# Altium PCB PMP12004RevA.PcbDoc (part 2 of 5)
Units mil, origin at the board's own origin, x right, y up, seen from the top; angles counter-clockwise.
Board outline 5500 x 4500 mil, 6 copper layers (Top Layer, GND, Signal Layer 1, Signal Layer 2, PWR Split, Bottom Layer), stack 0 mil thick; 355 components, 130 nets, 833 pads, 904 vias.
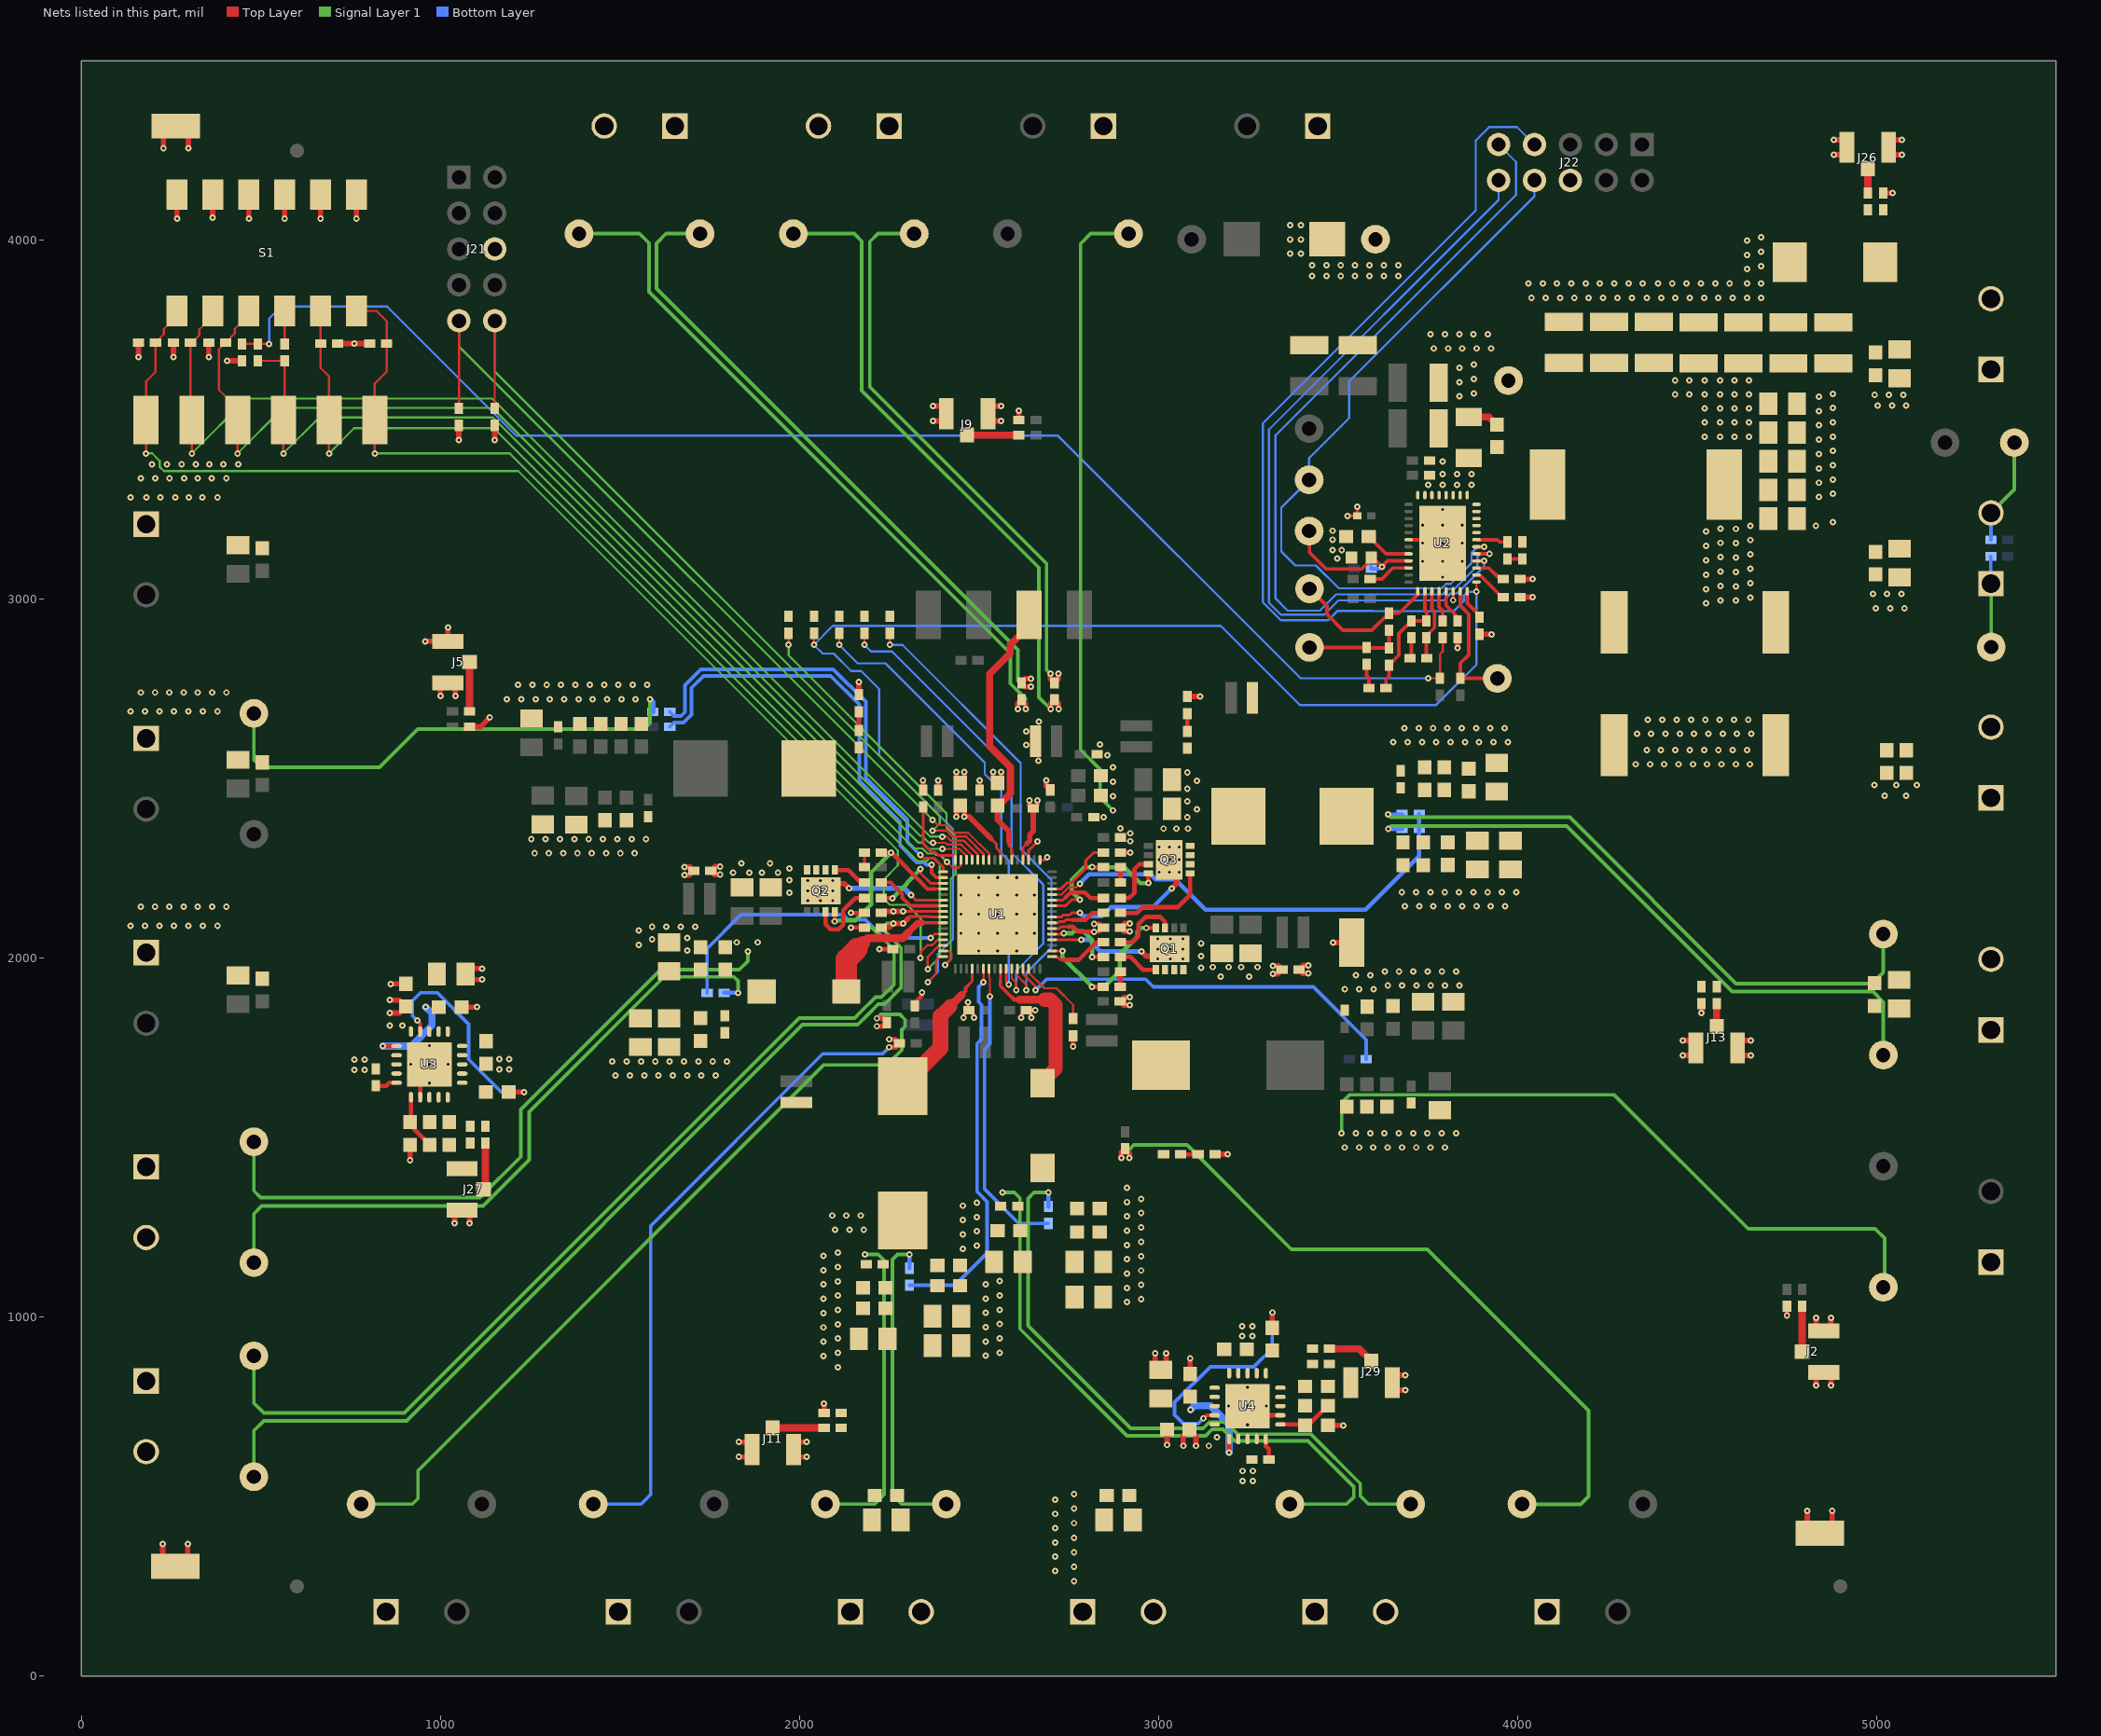
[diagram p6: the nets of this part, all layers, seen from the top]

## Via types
v1: diameter 18, hole 8, Top Layer to Bottom Layer, tented both sides, 835 vias
v2: diameter 19.68, hole 8.01, Top Layer to Bottom Layer, tented bottom, 42 vias
v3: diameter 18, hole 8.01, Top Layer to Bottom Layer, tented bottom, 27 vias

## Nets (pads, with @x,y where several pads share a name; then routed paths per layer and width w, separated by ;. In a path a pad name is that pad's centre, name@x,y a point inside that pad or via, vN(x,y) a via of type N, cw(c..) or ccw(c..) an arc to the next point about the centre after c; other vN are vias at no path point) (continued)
BUCK3_OUT: C132.1 C133.1 C134.1 C135.1 C136.1 C137.1 C138.1 C139.1 C140.1 C141.1 L6.2 R80.2 TP49.1 U3.5 U3.6 U3.7 U3.8 U3.11 | length 2170.3
  Top Layer w12: v1(839.77,1755.42) U3.11@877.43,1755.42
  Signal Layer 1 w10: TP49.1@480,1152.02 480,1287.83 501.93,1309.76 983.98,1309.76 1118.23,1309.76 1246.79,1438.31 1246.79,1572.56 1622.57,1948.34 1817.82,1948.34 1828.64,1937.52 v1(1828.64,1903.59)
  Bottom Layer w12: R80.2@1789.84,1903.59 v1(1828.64,1903.59)
  Bottom Layer w20: v1(839.77,1755.42) 918.91,1755.42 976.29,1812.79 976.29,1846.56 v1(958.82,1864.03)
BUCK4_OUT: C146.1 C148.1 C149.1 C150.1 C151.1 C152.1 C153.1 C154.1 C155.1 C156.1 L7.2 R85.2 TP51.1 U4.5 U4.6 U4.7 U4.8 U4.11 | length 2011.8
  Top Layer w12: v1(3196.98,622.99) U4.11@3196.98,660.65
  Signal Layer 1 w10: v1(2693.42,1347.02) 2653.19,1347.02 2637.07,1330.9 2637.07,975.98 2922.58,690.47 3124.72,690.47 3142.02,707.77 3187.41,707.77 3221.42,673.76 3425.05,673.76 3562.54,536.28 3562.54,501.81 3585.35,479 TP51.1@3702.83,479
  Bottom Layer w12: R85.2@2693.42,1308.22 v1(2693.42,1347.02)
  Bottom Layer w20: v1(3089.59,741.7) 3100.73,752.84 3144.8,752.84 3196.98,700.66 v1(3196.98,622.99)
BUCK5_OUT: C53.1 C54.1 C56.1 C57.1 C58.1 C59.1 C60.1 C61.1 C62.1 C63.1 C64.1 C65.1 C66.1 J8.2 J12.2 L3.2 R1.1 R3.1 R38.1 R39.2 TP21.1 | length 908.6
  Signal Layer 1 w10: v1(2306.42,1175.02) 2273.72,1175.02 2258.86,1160.16 2258.86,505.25 2285.11,479 TP21.1@2409.13,479
  Bottom Layer w12: R39.2@2306.42,1136.22 v1(2306.42,1175.02)
  other v1: 2099.57,1243.77 2139.54,1243.77 2179.12,1243.77 2091.03,1283.14 2130.87,1283.14 2170.71,1283.14 2665.65,2550.44 2631.96,2594.59 2631.96,2632.59 2666.49,2659
BUCK6_OUT: C74.1 C75.1 C76.1 C77.1 C78.1 C79.1 C80.1 C81.1 C82.1 C83.1 C84.1 C85.1 C86.1 J14.2 L4.2 R7.1 R45.1 R47.2 TP25.1 | length 1732.3
  Signal Layer 1 w10: v1(3639.99,2400.59) 3647.93,2392.66 4146.27,2392.66 4609.18,1929.75 4988.09,1929.75 5019.33,1961 TP25.1@5019.33,2067.19
  Bottom Layer w12: v1(3639.99,2400.59) R47.2@3678.8,2400.59
CLK: J22.9 U2.5 | length 2289.6
  Top Layer w10: U2.5@3885.96,3126.85 v1(3922.24,3126.85)
  Bottom Layer w6: v1(3922.24,3126.85) 3896.96,3126.85 3888.15,3118.04 3888.15,3092.59 3824.81,3029.26 3806.9,3029.26 3791.75,3014.1 3495.14,3014.1 3449.6,2968.56 3360.11,2968.56 3326.39,3002.28 3326.39,3457.42 3996.31,4127.35 3996.31,4218.77 J22.9@3947.51,4267.57
CTL1: R10.1 S1.1 TP6.1 U1.13 | length 3474.8
  Top Layer w6: v1(179.93,3406.75) TP6.1@179.93,3499.79 179.93,3607.58 205.93,3633.58 R10.1@205.93,3715.79 229.44,3739.3 229.44,3753.87 265.93,3790.36 S1.1@265.93,3803.79 ; v1(2337.29,2000.73) 2337.29,2017.77 2356.21,2036.69 2370.43,2036.69 2385.34,2051.6 U1.13@2400.42,2051.6
  Signal Layer 1 w6: v1(179.93,3406.75) 196.86,3406.75 217.37,3386.23 217.37,3369.65 229.4,3357.61 1216.38,3357.61 2274.07,2299.92 2274.07,2258.53 2235.34,2219.79 2235.34,2165.55 2252.14,2148.75 2300.16,2148.75 2337.29,2111.62 v1(2337.29,2000.73)
CTL2: R16.1 S1.2 TP12.1 U1.60 | length 3220.6
  Top Layer w6: v1(307.33,3406.75) TP12.1@307.33,3499.79 303.55,3503.57 R16.1@303.55,3715.79 307.43,3715.79 327.93,3736.29 327.93,3752.66 365.93,3790.66 S1.2@365.93,3803.79 ; v1(2397.73,2338.94) 2410.33,2338.94 2421.45,2327.81 2458.09,2327.81 2496.87,2289.03 U1.60@2496.87,2274.04
  Signal Layer 1 w6: v1(307.33,3406.75) 459.89,3559.31 1143.67,3559.31 2364.04,2338.94 v1(2397.73,2338.94)
CTL3/SLPENB1: R14.1 S1.3 TP9.1 U1.61 | length 3080.5
  Top Layer w6: v1(434.73,3406.75) TP9.1@434.73,3499.79 434.73,3531.98 382.97,3583.74 382.97,3697.21 R14.1@401.55,3715.79 401.91,3715.79 427.12,3741.01 427.12,3753.43 465.93,3792.23 S1.3@465.93,3803.79 ; v1(2371.96,2321.78) 2406.67,2321.78 2411.64,2316.81 2450.23,2316.81 2481.13,2285.91 U1.61@2481.13,2274.04
  Signal Layer 1 w6: v1(434.73,3406.75) 561.41,3533.43 1144.26,3533.43 2336.55,2341.14 2341.54,2341.14 2360.9,2321.78 v1(2371.96,2321.78)
CTL4: R12.2 R19.1 TP7.1 U1.62 | length 2802.4
  Top Layer w6: R12.2@490.86,3664.63 R19.1@565.93,3664.63 565.93,3497.73 TP7.1@562.13,3493.93 ; v1(562.13,3406.75) TP7.1@562.13,3493.93 ; TP7.1@562.13,3499.79 TP7.1@562.13,3493.93 ; v1(2397.73,2304.78) 2445.62,2304.78 2465.38,2285.02 U1.62@2465.38,2274.04
  Signal Layer 1 w6: v1(562.13,3406.75) 662.53,3507.15 1145.89,3507.15 2330.36,2322.67 2342.21,2322.67 2360.1,2304.78 v1(2397.73,2304.78)
CTL4_2: R11.1 R12.1 R58.2 R60.1 | length 3966.9
  Top Layer w6: R11.1@446.92,3711.79 R12.1@490.86,3711.79 ; R12.1@490.86,3711.87 v1(522.87,3711.87) ; v1(3751.7,2780) R58.2@3784.23,2780 3784.23,2847.22 3792,2854.99 R60.1@3792,2892.76
  Bottom Layer w6: v1(522.87,3711.87) 522.87,3782.99 555.57,3815.69 851.46,3815.69 1211.18,3455.96 2720.18,3455.96 3396.14,2780 v1(3751.7,2780)
CTL5: R13.1 S1.5 TP8.1 U1.63 | length 2720.9
  Top Layer w6: S1.5@665.93,3803.79 665.93,3644.8 689.53,3621.19 TP8.1@689.53,3499.79 v1(689.53,3406.75) ; v1(2410.91,2268.56) 2427.2,2252.26 2442.65,2252.26 2449.63,2259.25 U1.63@2449.63,2274.04
  Signal Layer 1 w6: v1(689.53,3406.75) 759.64,3476.86 1148.62,3476.86 2319.43,2306.05 2342.34,2306.05 2356.79,2291.6 2377.36,2291.6 2381.19,2287.78 2391.68,2287.78 v1(2410.91,2268.56)
CTL6/SLPENB2: R17.1 S1.6 TP14.1 U1.14 | length 2878.3
  Top Layer w6: S1.6@765.93,3803.79 821.59,3803.79 850.05,3775.33 R17.1@850.05,3712.79 850.05,3634.75 816.93,3601.62 TP14.1@816.93,3549.79 ; v1(816.93,3406.75) TP14.1@816.93,3499.79 ; v1(2357.37,1970.01) 2357.42,2004.09 2389.19,2035.85 U1.14@2400.42,2035.85
  Signal Layer 1 w6: v1(816.93,3406.75) 1192.9,3406.75 2329.29,2270.36 2353.85,2270.36 2360.95,2277.47 2375.03,2277.47 2391.09,2261.41 2391.09,2003.74 v1(2357.37,1970.01)
DATA: J22.10 U2.4 | length 2147.3
  Top Layer w10: U2.4@3885.96,3107.17 v1(3907.28,3107.17)
  Bottom Layer w6: v1(3907.28,3107.17) 3907.28,3091.72 3832.07,3016.5 3814.12,3016.5 3794.74,2997.12 3501.56,2997.12 3461.99,2957.56 3341.02,2957.56 3307.88,2990.7 3307.88,3473.02 3947.51,4112.65 J22.10@3947.51,4167.57
DRV5V_1_6: C3.1 R8.2 U1.38 | length 247.2
  Top Layer w8: U1.38@2703.57,2083.1 2724.26,2083.1 2728.87,2087.71 2750.64,2087.71
  Top Layer w12: 2750.64,2087.71 2762.82,2087.71 2776.54,2073.99 v1(2820.79,2073.99) 2835.19,2073.99 C3.1@2846.8,2085.59 2836.28,2096.11 v1(2820.79,2096.11)
  Top Layer w15: v1(3318.41,1956.99) 3332.82,1956.99 R8.2@3344.42,1968.59 3333.91,1979.11 v1(3318.41,1979.11)
DRV5V_2_A1: C2.1 R9.2 U1.8 | length 235.1
  Top Layer w8: v1(2288.87,2130.34) U1.8@2400.42,2130.34
  Top Layer w15: v1(1779.05,2233.08) 1763.55,2233.08 R9.2@1753.04,2243.59 1764.64,2255.2 v1(1779.05,2255.2) ; C2.1@2228.04,2126.59 2231.79,2130.34 v1(2261.42,2130.34) v1(2288.87,2130.34)
DRVH1: R22.1 U1.33 | length 167.3
  Top Layer w8: U1.33@2703.57,2004.36 2717.94,2004.36 2726.84,1995.46 2736.26,1995.46 2736.45,1995.65
  Top Layer w12: 2736.45,1995.65 2777.8,1995.65 2826.74,2044.59 R22.1@2846.8,2044.59
DRVH2: R30.1 U1.3 | length 230.6
  Top Layer w8: v1(2336.99,2248.47) 2336.99,2237.4 2365.31,2209.08 U1.3@2400.42,2209.08
  Top Layer w12: R30.1@2228.04,2167.59 v1(2259.42,2167.59)
  Signal Layer 1 w12: v1(2259.42,2167.59) 2299.54,2207.72 2299.54,2211.02 v1(2336.99,2248.47)
DRVH6: R43.1 U1.43 | length 158.7
  Top Layer w8: U1.43@2703.57,2161.84 2733.77,2161.84 2741.13,2169.2
  Top Layer w12: 2741.13,2169.2 2742.01,2170.08 2742.2,2170.08 2755.51,2183.4 2795.26,2183.4 2811.06,2167.59 R43.1@2846.8,2167.59
DRVL1: R23.1 U1.37 | length 203.9
  Top Layer w8: U1.37@2703.57,2067.35 2733.96,2067.35 v1(2736.32,2069.71)
  Top Layer w12: v1(2815.5,2003.59) R23.1@2846.8,2003.59
  Signal Layer 1 w12: v1(2736.32,2069.71) 2759.42,2069.71 2765.36,2075.65 2790.27,2075.65 2815.5,2050.42 v1(2815.5,2003.59)
DRVL2: R31.1 U1.7 | length 205.3
  Top Layer w8: 2385.05,2146.09 U1.7@2400.42,2146.09
  Top Layer w10: R31.1@2228.04,2211.59 2253.42,2211.59 2286.51,2178.5 2286.51,2168.67 2309.09,2146.09 2385.05,2146.09
DRVL6: R44.1 U1.39 | length 154.7
  Top Layer w8: U1.39@2703.57,2098.85 2721.62,2098.85 2724.37,2101.59 2736.78,2101.59 2742.17,2106.99 2760.78,2106.99
  Top Layer w12: 2760.78,2106.99 2796.64,2106.99 2816.24,2126.59 R44.1@2846.8,2126.59
FB3: R80.1 U1.12 | length 851.7
  Top Layer w6: v1(2365.23,2056.92) 2375.66,2067.35 U1.12@2400.42,2067.35
  Bottom Layer w10: R80.1@1742.6,1903.59 1742.6,2027.16 1837.17,2121.74 2121.4,2121.74 2135.55,2107.59 2183.9,2107.59 2234.58,2056.92 v1(2365.23,2056.92)
FB4: R85.1 U1.23 | length 838.4
  Top Layer w6: U1.23@2528.37,1970.89 2528.37,1946.43 2530.24,1944.57 v1(2530.24,1893.65)
  Bottom Layer w10: v1(2530.24,1893.65) 2530.24,1761.33 2515.74,1746.83 2515.74,1356.46 2611.22,1260.97 R85.1@2693.42,1260.97
FB5: R39.1 U1.22 | length 1071.8
  Top Layer w6: v1(2512.62,1933.41) U1.22@2512.62,1970.89
  Bottom Layer w10: R39.1@2306.42,1088.97 2432.91,1088.97 2523.51,1179.57 2522.7,1180.38 2522.7,1321.59 2494.63,1349.66 2494.63,1762.28 2506.86,1774.51 2506.86,1870.34 2499.14,1878.06 2499.14,1919.93 v1(2512.62,1933.41)
FBGND2: R35.1 U1.1 | length 1266.7
  Top Layer w8: v1(2336.99,2287.36) 2345.6,2278.75 2375.26,2278.75 2400.42,2253.59 U1.1@2400.42,2240.58
  Bottom Layer w10: R35.1@1638.66,2686.22 1649.53,2675.35 1669.92,2675.35 1680.68,2686.11 1680.68,2761.01 1724.91,2805.24 2094.47,2805.24 2184.73,2714.98 2184.73,2501.8 2300.43,2386.11 2300.43,2323.92 v1(2336.99,2287.36)
FBVOUT1: R26.1 U1.29 | length 1131.2
  Top Layer w6: U1.29@2622.86,1970.89 2622.86,1956.88 2658.06,1921.68 v1@2658.06,1912.29
  Bottom Layer w10: v1(2658.06,1911.13) 2688.79,1941.87 2963.86,1941.87 2985.83,1919.9 3432.06,1919.9 3579.04,1772.91 R26.1@3579.04,1718.59
FBVOUT2: R34.1 U1.2 | length 1275
  Top Layer w8: U1.2@2390.82,2225.18 2391.17,2224.83 U1.2@2400.42,2224.83
  Top Layer w10: v1(2367.99,2260.47) 2367.99,2237.72 2380.88,2224.83 U1.2@2391.17,2224.83
  Bottom Layer w10: R34.1@1638.66,2645.22 1650.51,2657.07 1677.5,2657.07 1698.97,2678.54 1698.97,2753.44 1732.48,2786.96 2086.9,2786.96 2166.45,2707.4 2166.45,2494.23 2280.37,2380.31 2280.37,2313.46 2326.36,2267.47 2346.14,2267.47 2353.14,2260.47 v1(2367.99,2260.47)
FBVOUT6: R47.1 R48.2 U1.44 | length 1266.4
  Top Layer w6: U1.44@2703.57,2177.59 2729.71,2177.59 2736.21,2184.08 2736.4,2184.08 2749.71,2197.4 2770.63,2197.4 v1(2780.69,2207.45)
  Bottom Layer w12: v1(2780.69,2207.45) 2806.82,2233.59 2977.71,2233.59 2991.93,2219.38 3046.42,2219.38 3130.81,2134.99 3577.26,2134.99 3726.4,2284.13 R48.2@3726.4,2360.47 R47.1@3726.4,2401.91
GND: C1.2 C2.2 C3.2 C4.2 C5.2 C6.2 C7.2 C8.2 C9.2 C10.2 C11.2 C12.2 C13.2 C14.2 C15.2 C16.2 C17.2 C19.2 C20.2 C21.2 C22.2 C23.2 C24.2 C25.2 C26.2 C27.2 C28.2 C29.2 C30.2 C32.2 C33.2 C34.2 C35.2 C36.2 C37.2 C38.2 C39.2 C40.2 C41.2 C42.2 C43.2 C44.2 C45.2 C46.2 C47.2 C48.2 C49.2 C50.2 C51.2 C52.2 C53.2 C54.2 C55.2 C56.2 C57.2 C58.2 C59.2 C60.2 C61.2 C62.2 C63.2 C64.2 C65.2 C66.2 C67.2 C68.2 C69.2 C70.2 C72.2 C73.2 C74.2 C75.2 C76.2 C77.2 C78.2 C79.2 C80.2 C81.2 C82.2 C83.2 C84.2 C85.2 C86.2 C87.2 C88.2 C89.2 C90.2 C91.2 C92.2 C93.2 C97.2 C98.2 C99.2 C101.2 C102.2 C103.2 C104.2 C105.2 C106.2 C107.2 C108.2 C111.2 C112.2 C113.2 C114.2 C115.2 C116.2 C117.2 C118.2 C119.2 C120.2 C121.2 C122.2 C123.2 C124.2 C125.2 C126.2 C127.2 C128.2 C129.2 C130.2 C131.2 C132.2 C133.2 C134.2 C135.2 C136.2 C137.2 C138.2 C139.2 C140.2 C141.2 C142.2 C143.2 C144.2 C145.2 C146.2 C147.2 C148.2 C149.2 C150.2 C151.2 C152.2 C153.2 C154.2 C155.2 C156.2 C157.2 C158.2 J1.1 J2.2 J2.3 J3.1 J4.1 J5.2 J5.3 J6.1 J7.1 J8.1 J9.2 J9.3 J10.1 J11.2 J11.3 J12.1 J13.2 J13.3 J14.1 J15.1 J16.1 J17.1 J18.1 J19.1 J20.1 J21.6 J22.6 J23.1 J24.1 J25.1 J26.2 J26.3 J27.2 J27.3 J28.1 J29.2 J29.3 J30.1 Q1.9 Q2.9 Q3.9 R27.2 R35.2 R36.2 R48.1 R49.2 R62.2 R65.2 R67.2 R69.2 R73.2 R75.1 R79.1 R84.1 S1.7 S1.8 S1.9 S1.10 S1.11 S1.12 TP2.1 TP3.1 TP4.1 TP5.1 TP18.1 TP20.1 TP22.1 TP24.1 TP26.1 TP30.1 TP31.1 TP32.1 TP36.1 TP37.1 TP38.1 TP48.1 TP50.1 TP52.1 U1.6 U1.36 U1.40 U1.52 U1.65 U2.13 U2.14 U2.15 U2.16 U2.17 U2.18 U2.19 U2.20 U2.26 U2.38 U2.41 U3.2 U3.3 U3.4 U3.12 U3.13 U3.14 U3.17 U3.21 U4.2 U4.3 U4.4 U4.12 U4.13 U4.14 U4.17 U4.21 | length 30114.8
  Top Layer w8: v1(2310.49,2175.97) 2324.62,2161.84 U1.6@2400.42,2161.84 ; U1.52@2622.86,2274.04 2622.86,2308.53 2634.37,2320.05 ; U1.36@2703.57,2051.6 v1(2785.08,2051.6) ; U1.40@2703.57,2114.59 2729.05,2114.59 2734.55,2120.09 2752.67,2120.09 2759.92,2127.34 v1(2780.69,2127.34)
  Top Layer w10: v1(2457.01,1834.29) 2457.01,1840.81 C7.2@2471.8,1855.59 ; v1(2469.55,1876.94) 2469.55,1857.84 C7.2@2471.8,1855.59 ; v1(2486.12,1834.29) 2486.12,1841.27 C7.2@2471.8,1855.59 ; v1(2617.25,1834.29) 2617.25,1840.81 C6.2@2632.04,1855.59 ; v1(2646.36,1834.29) 2646.36,1841.27 C6.2@2632.04,1855.59 ; v1(2657.03,1854.88) 2656.32,1855.59 C6.2@2632.04,1855.59 ; v1(3526.68,3232.68) C108.2@3553.59,3232.68 v1(3553.6,3258) ; U2.26@3696.98,3166.22 3781.63,3166.22 v2(3791.47,3156.38) ; v1(3821,2997.73) U2.38@3821,3022.52
  Top Layer w12: U3.17@943.37,1612.7 943.37,1678.65 v2(968.96,1704.24) ; v1(2143.42,2085.59) C88.2@2180.8,2085.59 ; v1(2143.42,2126.59) C2.2@2180.8,2126.59 ; v1(2222.8,2025.59) C5.2@2260.17,2025.59 ; C10.2@2320.92,1867.22 2320.92,1875.28 2341.58,1895.94 v1(2341.58,1904.3) ; R49.2@2894.04,2294.59 v1(2921.09,2294.59) ; v2(3248.17,752.19) 3273.76,726.6 U4.17@3339.7,726.6
  Top Layer w15: v1(226.37,368.2) 226.37,306.07 TP3.1@261.14,306.07 295.91,306.07 v1(295.91,368.2) ; v1(228.16,4256.66) 228.16,4318.79 TP5.1@262.93,4318.79 297.7,4318.79 v1(297.7,4256.66) ; v1(265.93,4060.69) S1.12@265.93,4127.79 ; v1(364.99,4063.15) S1.11@364.99,4130.25 ; v1(465.93,4060.69) S1.10@465.93,4127.79 ; v1(565.93,4060.69) S1.9@565.93,4127.79 ; v1(665.93,4060.69) S1.8@665.93,4127.79 ; v1(765.93,4060.69) S1.7@765.93,4127.79 ; v1(860.92,1928.53) C143.2@903.96,1928.53 ; v1(915.26,1437.3) R79.1@915.26,1480.34 ; v1(957.69,2883.29) 1014.69,2883.29 J5.3@1017.64,2886.24 ; v1(999.8,2730.6) 999.8,2767.15 J5.2@1020.59,2767.15 1041.39,2767.15 v1(1041.39,2730.6) ; J5.3@1020.59,2883.29 v1(1020.59,2921.69) ; v1(1039.17,1261.16) 1039.17,1297.71 J27.2@1059.96,1297.71 1080.76,1297.71 v1(1080.76,1261.16) ; C141.2@1058.46,1864.03 v1(1101.5,1864.03) ; C49.2@1080.63,2645.31 1111.88,2645.31 v1(1137.28,2670.7) ; v1(1115.85,1940.64) 1085.36,1940.64 C140.2@1069.97,1956.03 1085.36,1971.43 v1(1115.85,1971.43) ; v1(1830.95,610.5) 1867.5,610.5 J11.3@1867.5,631.29 1867.5,652.08 v1(1830.95,652.08) ; v1(2020.19,610.5) 1983.64,610.5 J11.2@1983.64,631.29 1983.64,652.08 v1(2020.19,652.08) ; Q2.9@2059.8,2187.59 2080.26,2208.06 2125.37,2208.06 v1(2138.36,2195.07) ; C64.2@2068.6,733.53 v1(2068.6,759.55) ; C50.2@2165.22,2734.37 v1(2165.22,2769.82) ; v1(2215.41,1810.46) 2232.91,1810.46 C91.2@2243.42,1820.97 2231.82,1832.57 v1(2215.41,1832.57) ; v1(2250.17,1752.08) 2267.66,1752.08 C92.2@2278.17,1762.59 2266.57,1774.2 v1(2250.17,1774.2) ; v1(2344.01,2495.96) 2344.42,2495.55 R36.2@2344.42,2468.84 ; v1(2372.5,3496.93) 2409.05,3496.93 J9.2@2409.05,3517.72 2409.05,3538.52 v1(2372.5,3538.52) ; v1(2386.01,2495.96) 2386.42,2495.55 C15.2@2386.42,2468.84 ; v1(2437.38,2518.59) 2437.38,2499.63 C13.2@2448.42,2488.59 2459.49,2499.66 v1(2459.49,2518.59) ; v1(2502.01,2495.96) 2502.42,2495.55 C11.2@2502.42,2468.84 ; v1(2539.77,2519.28) 2539.77,2500.23 C14.2@2551.42,2488.59 2561.89,2499.06 v1(2561.89,2519.28) ; v1(2561.74,3496.93) 2525.19,3496.93 J9.3@2525.19,3517.72 2525.19,3538.52 v1(2561.74,3538.52) ; C55.2@2611.46,3499.8 v1(2611.46,3525.82) ; 2634.37,2320.05 2641.31,2326.99 2641.31,2344.18 2651.42,2354.28 C12.2@2651.42,2417.59 ; v1(2640.34,2440.32) 2640.34,2428.67 C12.2@2651.42,2417.59 ; v1(2644.43,2756.7) 2628.93,2756.7 C89.2@2618.42,2767.22 2630.02,2778.82 v1(2644.43,2778.82) ; v1(2662.46,2440.32) 2662.46,2428.63 C12.2@2651.42,2417.59 ; v1(2687.19,2495.22) 2687.19,2480.82 C8.2@2698.8,2469.22 ; v1(2698.82,2793.22) 2698.82,2778.82 C90.2@2710.42,2767.22 2720.93,2777.73 v1(2720.93,2793.22) ; v1(2762.42,1754.15) R27.2@2762.42,1784.35 ; v1(2896.91,1443.34) 2896.91,1458.84 C93.2@2907.42,1469.35 2919.02,1457.75 v1(2919.02,1443.34) ; v1(2919.67,1869.08) 2904.18,1869.08 C9.2@2893.66,1879.59 2905.27,1891.2 v1(2919.67,1891.2) ; v1(2920.05,2075.08) 2904.55,2075.08 C3.2@2894.04,2085.59 2905.64,2097.2 v1(2920.05,2097.2) ; v1(2952.65,2018.85) 2965.64,2005.86 3010.75,2005.86 Q1.9@3031.21,2026.33 ; v1(2990.97,899.08) 2990.97,868.59 C155.2@3006.37,853.19 3021.76,868.59 v1(3021.76,899.08) ; v1(3023.87,644.15) C157.2@3023.87,687.19 ; Q3.9@3029.65,2273.19 3050.11,2252.73 3050.11,2207.61 v1(3037.13,2194.63) ; C87.2@3080.48,2729.15 v1(3115.94,2729.15) ; C156.2@3088.37,841.69 v1(3088.37,884.73) ; C30.2@3157.66,1453.59 v1(3193.12,1453.59) ; R84.1@3472.06,698.49 v1(3515.1,698.49) ; J29.3@3535.36,796.73 J29.3@3535.36,817.52 J29.3@3535.36,838.32 ; v1(3688.05,796.73) 3651.5,796.73 J29.2@3651.5,817.52 3651.5,838.32 v1(3688.05,838.32) ; v1(3833,2865) R62.2@3833,2892.76 ; R65.2@3894.23,2902.76 v1(3928.3,2902.76) ; R67.2@4007.85,3006.38 v1(4041.92,3006.38) ; R69.2@4007.85,3056.38 v1(4041.92,3056.38) ; v1(4460.63,1729.12) 4497.18,1729.12 J13.3@4497.18,1749.91 4497.18,1770.71 v1(4460.63,1770.71) ; v1(4513.05,1847.8) C86.2@4513.05,1873.82 ; v1(4649.87,1729.12) 4613.32,1729.12 J13.2@4613.32,1749.91 4613.32,1770.71 v1(4649.87,1770.71) ; v1(4751.01,1004.25) C29.2@4751.01,1030.27 ; v1(4807.38,459.9) 4807.38,397.77 TP4.1@4842.15,397.77 4876.92,397.77 v1(4876.92,459.9) ; v1(4832.46,809.27) 4832.46,845.83 J2.3@4853.25,845.83 4874.05,845.83 v1(4874.05,809.27) ; v1(4832.46,998.52) 4832.46,961.97 J2.2@4853.25,961.97 4874.05,961.97 v1(4874.05,998.52) ; v1(4881.51,4239.05) 4918.06,4239.05 J26.2@4918.06,4259.85 4918.06,4280.64 v1(4881.51,4280.64) ; C130.2@5019.68,4132.61 v1(5045.7,4132.61) ; v1(5070.75,4239.05) 5034.2,4239.05 J26.3@5034.2,4259.85 5034.2,4280.64 v1(5070.75,4280.64)
  Signal Layer 1 w10: TP30.1@480,892.02 480,760.58 507.84,732.74 898.65,732.74 1999.22,1833.32 2153.49,1833.32 2169.81,1849.64 2211.78,1891.59 2227.83,1891.59 2263.43,1927.2 2263.43,2023.65 2201.48,2085.59 v1(2143.42,2085.59) ; TP50.1@480,1488.87 480,1352.11 499.39,1332.72 1109.44,1332.72 1223.6,1446.88 1223.6,1578.19 1613.44,1968.02 1832.39,1968.02 1856.53,1992.17 v1(1856.53,2019.01) ; TP20.1@480,2682.57 480,2552.13 499.95,2532.18 830.31,2532.18 936.32,2638.19 1566.12,2638.19 1583.53,2655.6 v1(1583.53,2722.15) ; TP36.1@778.58,479 921.64,479 937.45,494.81 937.45,572.2 2068.14,1702.89 2243.49,1702.89 2284.83,1744.23 2284.83,1800.71 2294.65,1810.53 2294.65,1828.62 2279.97,1843.3 2226.14,1843.3 v1(2215.41,1832.57) ; TP32.1@1722.87,4019 1628.46,4019 1601.89,3992.43 1601.89,3866.2 2608.66,2859.44 2608.66,2773.79 2625.74,2756.7 v1(2644.43,2756.7) ; TP22.1@2072.28,479 2209.56,479 2235.95,505.39 2235.95,1158.55 2219.49,1175.02 v1(2182.26,1175.02) ; TP31.1@2319.72,4019 2218.45,4019 2196.09,3996.63 2196.09,3591.82 2688.46,3099.45 2688.46,2803.58 v1(2698.82,2793.22) ; v1(2565.57,1347.02) 2598.74,1347.02 2614.34,1331.43 2614.34,967.66 2912.44,669.56 3131.65,669.56 3149.3,687.22 3180.08,687.22 3212.01,655.29 3416.08,655.29 3544.49,526.88 3544.49,499.6 3523.89,479 TP52.1@3365.98,479 ; v1(2873.26,2411.86) 2837.86,2447.26 2837.86,2525.9 2782.96,2580.8 2782.96,3990.53 2811.44,4019 TP24.1@2916.57,4019 ; v1(2919.02,1443.34) 2919.02,1467.23 2931.36,1479.57 3079.87,1479.57 3370.39,1189.05 3748.44,1189.05 4198.06,739.43 4198.06,500.18 4176.09,478.21 4013.61,478.21 TP38.1@4012.83,479 ; v1(3510.39,1512.21) 3510.39,1597.77 3532,1619.38 4269.89,1619.38 4643.12,1246.14 4996.54,1246.14 5022.86,1219.82 5022.86,1087.02 TP18.1@5019.33,1083.49 ; v1(3640.36,2360.47) 3648.38,2368.5 4137.01,2368.5 4598.48,1907.03 4990.21,1907.03 5019.33,1877.91 TP26.1@5019.33,1730.34 ; J24.1@5319.33,3044.04 5320.09,3043.29 TP48.1@5320.09,2867.18
  Bottom Layer w10: TP37.1@1425.43,479 1558.54,479 1585.34,505.8 1585.34,1254.34 2064.79,1733.78 2231.87,1733.78 v1(2250.17,1752.08) v1@2250.17,1750.99 ; v1@2215.41,1809.37 v1(2215.41,1810.46) ; R73.2@5318.8,3119.79 5318.8,3044.58 J24.1@5319.33,3044.04
  Bottom Layer w12: v1(2780.69,2127.34) 2790.81,2117.21 2841.92,2117.21 2867.12,2142.42 2984.92,2142.42 v1(3037.13,2194.63) ; v1(2785.08,2051.6) 2806.55,2051.6 2839.3,2018.85 v1(2952.65,2018.85) ; v1(3640.36,2360.47) R48.1@3679.16,2360.47
  Bottom Layer w15: v1(1583.53,2722.15) 1591.42,2714.26 R35.2@1591.42,2686.22 ; v1(2138.36,2195.07) 2291.39,2195.07 v1(2310.49,2175.97)
  other v1: 2765.03,263.96 2712.25,292.92 2765.03,304.41 2712.25,332.66 2765.03,344.86 2712.25,372.39 2765.03,385.32 2712.25,412.13 2765.03,425.77 2712.25,451.86 2765.03,466.22 2712.25,491.6 2765.03,506.67 3234.93,543.37 3262.84,543.37 3234.93,571.33 3262.84,571.33 2106.65,860.67 2067.29,891.46 2518.38,892.36 2106.65,900.51 2557.75,900.9 2067.29,931.43 2518.38,932.2 2106.65,940.35 2557.75,940.74 3233.71,946.9 3261.63,946.9 2067.29,971.4 2518.38,972.04 3233.71,974.87 3261.63,974.87 2106.65,980.19 2557.75,980.58 2067.29,1011.37 2518.38,1011.88 2106.65,1020.03 2557.75,1020.55 2912.64,1041.82 2952.01,1050.36 2067.29,1051.33 2518.38,1051.72 2106.65,1059.88 2557.75,1060.14 2912.64,1081.66 2952.01,1090.33 2067.29,1091.3 2518.38,1091.56 2106.65,1099.72 2557.75,1100.11 2912.64,1121.51 2952.01,1129.92 2067.29,1130.89 2106.65,1139.56 2912.64,1161.35 2952.01,1169.89 2067.29,1170.86 2106.65,1179.4 2454.75,1190.74 2494.11,1199.41 2912.64,1201.19 2952.01,1209.86 2454.75,1230.71 2494.11,1239.25 2912.64,1241.03 2952.01,1249.82 2454.75,1270.55 2494.11,1279.09 2912.64,1280.87 2952.01,1289.79 2454.75,1310.39 2494.11,1318.93 2912.64,1320.71 2952.01,1329.76 2912.64,1360.55 3518.93,1472.84 3558.9,1472.84 3598.48,1472.84 3638.45,1472.84 3678.42,1472.84 3718.39,1472.84 3758.36,1472.84 3798.33,1472.84 3550.23,1512.21 3590.07,1512.21 3629.91,1512.21 3669.75,1512.21 3709.59,1512.21 3749.43,1512.21 3789.27,1512.21 3829.11,1512.21 1487.88,1673.39 1527.73,1673.39 1567.57,1673.39 1607.41,1673.39 1647.25,1673.39 1687.09,1673.39 1726.93,1673.39 1766.9,1673.39 760.14,1689.56 788.11,1689.56 1163.68,1690.78 1191.64,1690.78 1478.83,1712.76 1518.67,1712.76 1558.51,1712.76 1598.48,1712.76 1638.45,1712.76 1678.42,1712.76 1718.39,1712.76 1758.36,1712.76 1798.33,1712.76 760.14,1717.48 788.11,1717.48 1163.68,1718.69 1191.64,1718.69 3519.51,1913.72 3559.35,1913.72 3599.2,1913.72 3639.04,1923.72 3678.88,1923.72 3718.72,1923.72 3758.56,1923.72 3798.4,1923.72 3838.24,1923.72 3172.93,1949.21 3252.93,1949.21 3550.3,1953.09 3590.27,1953.09 3630.24,1963.09 3670.21,1963.09 3710.18,1963.09 3750.15,1963.09 3789.73,1963.09 3829.7,1963.09 3119.31,1973.78 3150.85,1975.39 3195.69,1975.39 3230.85,1975.39 3275.69,1975.39 3119.31,2006.33 1687.7,2022.12 1552.28,2037.33 3119.31,2041.62 1825.43,2044.36 1883.22,2044.36 1589.45,2053.15 1687.7,2057.1 1552.28,2077.17 1589.45,2088.12 1629.41,2088.12 1669.38,2088.12 1709.35,2088.12 136.03,2090.97 176.48,2090.97 216.93,2090.97 257.38,2090.97 297.83,2090.97 338.28,2090.97 378.73,2090.97 164.99,2143.74 204.73,2143.74 244.46,2143.74 284.19,2143.74 323.93,2143.74 363.66,2143.74 403.4,2143.74 3686.55,2144.91 3726.52,2144.91 3766.11,2144.91 3806.08,2144.91 3846.04,2144.91 3886.01,2144.91 3925.98,2144.91 3965.95,2144.91 1971.7,2182.3 3678.01,2184.28 3717.85,2184.28 3757.69,2184.28 3797.53,2184.28 3837.38,2184.28 3877.22,2184.28 3917.06,2184.28 3956.9,2184.28 3996.74,2184.28 1971.7,2217.59 1815.32,2238.53 1860.16,2238.53 1895.32,2238.53 1940.16,2238.53 1971.7,2250.14 1838.08,2264.71 1918.08,2264.71 1262,2292.5 1301.84,2292.5 1341.69,2292.5 1381.53,2292.5 1421.37,2292.5 1461.21,2292.5 1501.05,2292.5 1540.89,2292.5 2921.09,2326.24 1252.95,2331.87 1292.79,2331.87 1332.76,2331.87 1372.73,2331.87 1412.7,2331.87 1452.67,2331.87 1492.64,2331.87 1532.6,2331.87 1572.57,2331.87 2921.09,2348.35 3014.36,2361.28 3049.64,2361.28 3082.2,2361.28 2894.65,2361.91 2847.64,2393.25 3080.59,2392.82 3106.76,2414.91 3080.59,2437.67 2873.26,2451.83 5023.32,2452.76 5082.95,2452.76 3080.59,2472.82 4994.53,2482.72 5055.62,2482.72 5112.62,2482.72 2873.26,2491.8 3106.76,2494.91 3080.59,2517.67 2873.26,2531.77 4329.39,2540.55 4369.23,2540.55 4409.07,2540.55 4448.91,2540.55 4488.75,2540.55 4528.59,2540.55 4568.43,2540.55 4608.27,2540.55 4648.11,2540.55 2857.92,2565.84 4360.17,2579.92 4400.14,2579.92 4440.11,2579.92 4480.08,2579.92 4520.05,2579.92 4560.02,2579.92 4599.6,2579.92 4639.57,2579.92 2837.05,2595.91 3654.47,2601.75 3694.31,2601.75 3734.16,2601.75 3774,2601.75 3813.84,2601.75 3853.68,2601.75 3893.52,2601.75 3933.36,2601.75 3973.2,2601.75 4332.97,2625.49 4372.81,2625.49 4412.65,2625.49 4452.49,2625.49 4492.33,2625.49 4532.17,2625.49 4572.01,2625.49 4611.86,2625.49 4651.7,2625.49 3685.26,2641.12 3725.23,2641.12 3765.2,2641.12 3805.17,2641.12 3845.14,2641.12 3885.11,2641.12 3924.69,2641.12 3964.66,2641.12 4363.76,2664.86 4403.73,2664.86 4443.7,2664.86 4483.66,2664.86 4523.63,2664.86 4563.6,2664.86 4603.19,2664.86 4643.16,2664.86 136.03,2687.82 176.48,2687.82 216.93,2687.82 257.38,2687.82 297.83,2687.82 338.28,2687.82 378.73,2687.82 1185.12,2722.15 1224.96,2722.15 1264.8,2722.15 1304.64,2722.15 1344.48,2722.15 1384.32,2722.15 1424.16,2722.15 1464,2722.15 1503.85,2722.15 1543.69,2722.15 164.99,2740.59 204.73,2740.59 244.46,2740.59 284.19,2740.59 323.93,2740.59 363.66,2740.59 403.4,2740.59 1215.91,2761.52 1255.88,2761.52 1295.84,2761.52 1335.81,2761.52 1375.78,2761.52 1415.75,2761.52 1455.72,2761.52 1495.69,2761.52 1535.66,2761.52 1575.63,2761.52 4998.7,2975 5038.67,2975 5078.25,2975 4990.16,3015 5030,3015 5069.84,3015 3498.03,3113.97 3485.17,3137.75 3510.49,3137.75 3485.17,3166.49 3485.17,3191.23 4831.54,3205.16 4879.37,3215 136.03,3284.67 180.87,3284.67 220.14,3284.67 260.87,3284.67 298.74,3284.67 337.01,3284.67 378.73,3284.67 4840,3285.09 4879.37,3294.15 3752,3319.52 3792,3319.52 3832,3319.52 3872,3319.52 4840,3325.06 4879.37,3333.99 164.99,3337.44 205.54,3337.44 244.99,3337.44 285.54,3337.44 323.4,3337.44 362.85,3337.44 403.4,3337.44 3792,3349.52 3832,3349.52 3872,3349.52 4840,3365.03 4879.37,3373.83 195.78,3376.81 238.3,3376.81 278.83,3376.81 318.3,3376.81 356.16,3376.81 395.5,3376.81 436.16,3376.81 3792,3384.52 4840,3405 4879.37,3413.67 4840,3444.97 4879.37,3453.51 4840,3484.94 4879.37,3493.35 4840,3524.52 4879.37,3533.19 5003.7,3540 5043.67,3540 5083.25,3540 4840,3564.49 3838.97,3565.53 4995.16,3570 5035,3570 5074.84,3570 4879.37,3573.03 3878.97,3573.94 3838.97,3605.37 3878.97,3613.91 3838.97,3645.21 3878.97,3653.88 3766.87,3699.1 3806.84,3699.1 3846.43,3699.1 3886.4,3699.1 3926.37,3699.1 3758.33,3739.1 3798.17,3739.1 3838.01,3739.1 3877.86,3739.1 3917.7,3739.1 4039.18,3840 4079.15,3840 4118.73,3840 4158.7,3840 4198.67,3840 4238.64,3840 4278.61,3840 4318.58,3840 4360.64,3840 4400.48,3840 4440.32,3840 4480.16,3840 4520,3840 4559.84,3840 4599.68,3840 4639.52,3840 4679.36,3840 4030.64,3880 4070.48,3880 4110.32,3880 4150.16,3880 4190,3880 4229.84,3880 4269.68,3880 4309.52,3880 4349.36,3880 4391.42,3880 4431.39,3880 4471.36,3880 4511.33,3880 4551.3,3880 4591.27,3880 4639.52,3880 4679.36,3880 3427.96,3901.05 3467.96,3901.05 3507.96,3901.05 3547.96,3901.05 3587.96,3901.05 3627.96,3901.05 3667.96,3901.05 4639.52,3920.51 4679.36,3928.92 3427.96,3931.05 3467.96,3931.05 3507.96,3931.05 3547.96,3931.05 3587.96,3931.05 3627.96,3931.05 3667.96,3931.05 4639.52,3960.09 3367.16,3963 3397.16,3963 4679.36,3968.76 4639.52,4000.06 3367.16,4003 3397.16,4003 4679.36,4008.6 3367.16,4043 3397.16,4043
  other v2: 3248.17,700.02 3196,752.19 3300.33,752.19 3248.17,804.35 968.96,1652.07 916.8,1704.24 1021.13,1704.24 968.96,1756.4 2498.8,2020.03 2551.99,2020.03 2605.18,2020.03 2449.55,2069.28 2498.8,2069.28 2551.99,2069.28 2605.18,2069.28 2654.43,2069.28 2449.55,2122.47 2498.8,2122.47 2551.99,2122.47 2605.18,2122.47 2654.43,2122.47 2449.55,2175.66 2498.8,2175.66 2551.99,2175.66 2605.18,2175.66 2654.43,2175.66 2498.8,2224.91 2551.99,2224.91 2605.18,2224.91 3791.47,3061.89 3736.35,3105.87 3791.47,3105.87 3846.59,3105.87 3736.35,3156.38 3846.59,3156.38 3736.35,3206.89 3791.47,3206.89 3846.59,3206.89 3791.47,3250.87
  other v3: 2997.74,1997.88 3032.74,1997.88 3067.74,1997.88 2997.74,2025.88 3032.74,2025.88 3067.74,2025.88 2997.74,2053.88 3032.74,2053.88 3067.74,2053.88 2023.27,2160.04 2058.27,2160.04 2093.27,2160.04 2023.27,2188.04 2058.27,2188.04 2093.27,2188.04 2023.27,2216.04 2058.27,2216.04 2093.27,2216.04 3002.09,2239.71 3030.09,2239.71 3058.09,2239.71 3002.09,2274.71 3030.09,2274.71 3058.09,2274.71 3002.09,2309.71 3030.09,2309.71 3058.09,2309.71
GPO1: J22.7 R53.1 U1.16 U2.1 | length 5915.6
  Top Layer w6: v1(2040.29,2873.3) R53.1@2040.29,2905.64 ; v1(2357.37,1933.62) 2379.93,1956.19 2379.93,1993.54 2390.75,2004.36 U1.16@2400.42,2004.36 ; v1(3885.96,3021.23) U2.1@3885.96,3048.11
  Bottom Layer w6: v1(2357.37,1933.62) 2385.61,1961.87 2385.61,2011.69 2427.91,2053.99 2427.91,2360.16 2221.78,2566.29 2221.78,2750.22 2171.66,2800.34 2144.26,2800.34 2095.67,2848.93 2064.66,2848.93 v1(2040.29,2873.3) 2093.57,2926.57 3172.76,2926.57 3393.5,2705.84 3773.84,2705.84 3885.96,2817.95 v1(3885.96,3021.23) 3861.43,3021.23 3850.46,3010.25 3850.46,2994.86 3822.86,2967.26 3597.56,2967.26 3596.66,2968.16 3499.55,2968.16 3473.39,2942 3340.86,2942 3290.88,2991.98 3290.88,3490.64 3884.01,4083.77 3884.01,4278.25 3921.9,4316.13 3998.95,4316.13 J22.7@4047.51,4267.57
GPO2: R55.1 U1.26 | length 1266.7
  Top Layer w6: v1(2110.79,2873.3) R55.1@2110.79,2905.64 ; U1.26@2575.62,1970.89 2575.62,1934.18 v1(2583.03,1926.76)
  Bottom Layer w6: v1(2110.79,2873.3) 2162.49,2821.6 2239.36,2821.6 2516.17,2544.79 2516.17,2513.24 2561.92,2467.49 2561.92,2293.15 2583.03,2272.03 v1(2583.03,1926.76)
GPO3: R52.1 U1.27 | length 1330.6
  Top Layer w6: v1(2181.29,2873.3) R52.1@2181.29,2905.64 ; U1.27@2591.36,1970.89 2591.36,1944.06 2603.82,1931.61 v1(2603.82,1911.13)
  Bottom Layer w6: v1(2181.29,2873.3) 2199.6,2854.99 2257.63,2854.99 2590.64,2521.98 2590.64,2293.98 2678.9,2205.72 2678.9,2040.3 2603.82,1965.22 v1(2603.82,1911.13)
GPO4: R54.1 U1.28 | length 1299.8
  Top Layer w6: v1(2251.79,2873.3) R54.1@2251.79,2905.64 ; U1.28@2607.11,1970.89 2607.11,1950.95 2631.58,1926.49 v1@2631.58,1912.07
  Bottom Layer w6: v1(2251.79,2873.3) 2286.97,2873.3 2616.33,2543.94 2616.33,2304.44 2702.13,2218.65 2702.13,2029.52 2631.58,1958.97 v1(2631.58,1911.13)
ILIM1: R27.1 U1.30 | length 210.6
  Top Layer w6: U1.30@2638.61,1970.89 2638.61,1959.92 2682.16,1916.36 2716.31,1916.36 2762.42,1870.25 R27.1@2762.42,1831.59
ILIM2: R36.1 U1.64 | length 215.5
  Top Layer w8: R36.1@2344.42,2421.59 2344.42,2319.1 2367.68,2295.84 2378.38,2295.84 2387.66,2286.56 2429.69,2286.56 2433.88,2282.36 U1.64@2433.88,2274.04
ILIM6: R49.1 U1.45 | length 198
  Top Layer w8: U1.45@2703.57,2193.33 2728.49,2193.33 2731.24,2196.08 2731.43,2196.08 2744.82,2209.48 2756.67,2209.48 2797.5,2250.31 2797.5,2272.17 2819.93,2294.59 R49.1@2846.8,2294.59
IRQB: R51.1 U1.15 | length 1194.5
  Top Layer w6: v1(1969.79,2873.3) R51.1@1969.79,2905.64 ; U1.15@2400.42,2020.11 2416.25,2020.11 2424.15,2012.2 2424.15,1999.31 v1(2406.03,1981.19)
  Signal Layer 1 w6: v1(1969.79,2873.3) 1969.79,2843.71 2409.85,2403.65 2409.85,2364.76 2434.82,2339.8 2434.82,2234.31 2421.55,2221.04 2421.55,1996.7 v1(2406.03,1981.19)
LDO3P3: C14.1 C143.1 C157.1 R10.2 R11.2 R13.2 R14.2 R16.2 R17.2 R51.2 R52.2 R53.2 R54.2 R55.2 R56.1 R57.1 TP15.1 U1.54 U3.10 U4.10 | length 1376.3
  Top Layer w8: 2583.53,2325.28 2583.53,2312.9 2591.36,2305.07 U1.54@2591.36,2274.04
  Top Layer w12: C143.1@903.96,1865.54 C143.1@906.01,1863.5 ; C157.1@3086.86,687.19 C157.1@3088.91,689.24
  Top Layer w15: v1(158.69,3674.79) R10.2@158.69,3715.79 ; v1(256.31,3674.79) R16.2@256.31,3715.79 ; v1(354.31,3674.79) R14.2@354.31,3715.79 ; v1(405.92,3664.55) R11.2@446.92,3664.55 ; R13.2@713.46,3712.79 v1(760.32,3712.79) R17.2@802.81,3712.79 ; v1@858.25,1847.71 886.14,1847.71 C143.1@903.96,1865.54 886.14,1883.36 v1@858.25,1883.36 ; v1(1051.26,3443.85) R56.1@1051.26,3484.85 ; v1(1151.26,3443.85) R57.1@1151.26,3484.85 ; C14.1@2551.42,2425.59 2551.42,2385.76 2583.53,2353.64 2583.53,2325.28 ; v1(3069.04,641.47) 3069.04,669.37 C157.1@3086.86,687.19 3104.69,669.37 v1(3104.69,641.47)
  Top Layer w20: C14.1@2551.42,2425.59 2554.07,2425.59 2587.55,2459.08 2587.55,2533.02 2530.14,2590.43 2530.14,2792.53 2587.26,2849.65 2587.26,2873.52 2639.42,2925.67 TP15.1@2639.42,2956.59 TP15.1@2639.42,2994.74
  other v1: 3140.3,641.47 3163.33,665.83 858.24,1812.1 893.89,1812.1 858.24,1847.71 858.24,1883.36
LDO5V: C13.1 R8.1 R9.1 TP13.1 U1.56 | length 415.1
  Top Layer w8: 2533.69,2333.42 2548.58,2318.54 2548.58,2307.28 2559.87,2295.99 U1.56@2559.87,2274.04
  Top Layer w15: v1(1679.79,2231.99) 1694.19,2231.99 R9.1@1705.8,2243.59 1695.28,2254.11 v1(1679.79,2254.11) ; v1(2437.38,2394.85) 2437.38,2414.55 C13.1@2448.42,2425.59 2459.49,2414.52 v1(2459.49,2394.85) 2472.26,2394.85 2533.69,2333.42 ; v1(3417.67,1958.08) 3402.18,1958.08 R8.1@3391.66,1968.59 3403.27,1980.2 v1(3417.67,1980.2) ; v1(3486.43,2043.91) TP13.1@3538.65,2043.91
LDOA1: C88.1 J15.2 TP27.1 U1.9 | length 2849.9
  Top Layer w8: 2301.54,2109.67 2308.71,2116.85 2360.15,2116.85 2362.4,2114.59 U1.9@2400.42,2114.59
  Top Layer w15: C88.1@2228.04,2085.59 2250.01,2085.59 v1(2261.42,2097) v1(2288.87,2097) 2301.54,2109.67
  Signal Layer 1 w10: TP27.1@480,555.17 480,683.33 508.02,711.34 905.21,711.34 2008.74,1814.86 2162.34,1814.86 2188.47,1840.99 2219.31,1871.84 2237.42,1871.84 2282.86,1917.27 2282.86,2030.16 2234.74,2078.28 2234.74,2088.72 2243.03,2097 v1(2261.42,2097)
LDOA2: C89.1 J16.2 TP28.1 U1.51 | length 2061.3
  Top Layer w8: U1.51@2638.61,2274.04 2638.61,2300.96 2641.19,2303.55 v1(2662.81,2325.17)
  Top Layer w15: v1(2607.91,2693.97) 2607.91,2709.46 C89.1@2618.42,2719.97 2630.02,2708.37 v1(2630.02,2693.97)
  Signal Layer 1 w10: TP28.1@1386.02,4019 1554.44,4019 1580.68,3992.77 1580.68,3856.81 2587.74,2849.74 2587.74,2765.39 2630.02,2723.11 v1(2630.02,2693.97)
LDOA3: C90.1 J17.2 TP29.1 U1.49 | length 1806.2
  Top Layer w8: U1.49@2670.1,2274.04 2683.13,2274.04 v1(2690.54,2281.45)
  Top Layer w15: v1(2699.91,2693.97) 2699.91,2709.46 C90.1@2710.42,2719.97 2722.02,2708.37 v1(2722.02,2693.97)
  Signal Layer 1 w10: TP29.1@1982.87,4019 2152.71,4019 2173.64,3998.07 2173.64,3581.79 2666.72,3088.72 2666.72,2727.15 v1(2699.91,2693.97)
LX3: L6.1 U1.10 | length 401.2
  Top Layer w8: 2377.47,2098.85 U1.10@2400.42,2098.85
  Top Layer w10: 2342.02,2098.85 2377.47,2098.85
  Top Layer w18: 2303.4,2072.1 2330.15,2098.85 2342.02,2098.85
  Top Layer w22: 2176.24,2042.21 2189.63,2055.59 2286.9,2055.59 2303.4,2072.1
  Top Layer w40: 2160.44,2026.4 2176.24,2042.21
  Top Layer w60: L6.1@2130.53,1907.59 2130.53,1996.49 2160.44,2026.4
LX4: L7.1 U1.25 | length 451.7
  Top Layer w8: 2559.87,1937.83 U1.25@2559.87,1970.89
  Top Layer w10: 2559.87,1937.83 2559.87,1923.05 2591.95,1890.97
  Top Layer w12: 2591.95,1890.97 2597.99,1884.93 2613.42,1884.93
  Top Layer w22: 2613.42,1884.93 2683.05,1884.93
  Top Layer w40: L7.1@2677.42,1656.7 2713.51,1692.79 2713.51,1870.06 2698.64,1884.93 2683.05,1884.93
LX5: L3.1 U1.20 | length 402.7
  Top Layer w8: 2468.76,1923.3 2481.13,1935.66 U1.20@2481.13,1970.89
  Top Layer w10: 2451.6,1897.56 2462.86,1908.81 2462.86,1917.39 2468.76,1923.3
  Top Layer w22: 2420.58,1866.54 2451.6,1897.56
  Top Layer w40: 2392.64,1838.6 2420.19,1866.15
  Top Layer w45: L3.1@2287.42,1653.59 2297.2,1653.59 2392.64,1749.04 2392.64,1838.6
NetC18_2: C18.2 R20.2 | length 42.2
  Top Layer w15: C18.2@2893.66,1920.59 2893.66,1962.22 R20.2@2894.04,1962.59
NetC30_1: C30.1 R25.1 | length 48.8
  Top Layer w12: R25.1@3061.66,1453.59 C30.1@3110.42,1453.59
NetC31_2: C31.2 R28.2 | length 41
  Top Layer w8: R28.2@2180.8,2253.59 C31.2@2180.8,2294.59
NetC50_1: C50.1 R32.1 | length 52.8
  Top Layer w12: R32.1@2165.22,2634.37 C50.1@2165.22,2687.12
NetC71_2: C71.2 R41.2 | length 42
  Top Layer w12: R41.2@2894.04,2211.59 C71.2@2894.04,2253.59
NetC87_1: C87.1 R46.1 | length 49.4
  Top Layer w12: R46.1@3080.48,2632.52 C87.1@3080.48,2681.9
NetC94_1: C94.1 C96.1 R59.1 R63.2 U2.34 | length 343.4
  Top Layer w10: C96.1@3633.85,2752.38 3633.85,2777.04 3642.04,2785.22 R63.2@3642.04,2816.94 3669.59,2844.5 3669.59,2904.59 R59.1@3705,2940 C94.1@3746.23,2940 3747.35,2941.13 3747.35,2963.61 3742.26,2968.7 U2.34@3742.26,3022.52
NetC94_2: C94.2 C95.2 U2.35 | length 199.1
  Top Layer w10: C95.2@3747.85,2836.38 3746.23,2838 C94.2@3746.23,2892.76 3746.23,2898.3 3768.93,2921 3768.93,2966.42 3761.94,2973.41 U2.35@3761.94,3022.52
NetC95_1: C95.1 R59.2 | length 58.2
  Top Layer w10: C95.1@3700.61,2836.38 3705,2840.77 R59.2@3705,2892.76
NetC96_2: C96.2 R66.1 | length 69
  Top Layer w10: R66.1@3580.23,2818.76 3580.23,2786.61 3586.58,2780.25 C96.2@3586.61,2752.38
NetC97_1: C97.1 C98.1 C99.1 C101.1 C102.1 C103.1 C105.1 C106.1 C111.1 C118.1 C119.1 C120.1 C121.1 C122.1 C123.1 C124.1 C125.1 C126.1 C127.1 C128.1 C129.1 C130.1 J23.2 J24.2 J25.2 L5.2 R70.2 R74.1 TP47.1 | length 297.7
  Signal Layer 1 w10: J24.2@5319.33,3240.89 5384.39,3305.96 TP47.1@5384.39,3436.89
  Bottom Layer w10: R70.2@5319.06,3166.2 5319.06,3240.62 J24.2@5319.33,3240.89
  other v1: 4526.11,2989.21 4609.22,2996.88 4565.48,2997.62 4649.3,3005.29 4526.11,3028.8 4609.22,3036.46 4565.48,3037.47 4649.3,3045.13 4526.11,3068.76 4609.22,3076.43 4565.48,3077.31 4649.3,3085.06 4526.11,3109.31 4609.22,3116.97 4565.48,3117.72 4649.3,3125.39 4526.11,3148.89 4609.22,3156.56 4565.48,3157.56 4649.3,3165.23 4526.11,3188.86 4565.48,3197.4 4609.22,3196.53 4649.3,3205.16 4522.21,3453.07 4565.05,3453.07 4605.32,3453.07 4644.69,3453.07 4522.21,3492.91 4565.05,3492.91 4605.32,3492.91 4644.69,3492.91 4522.21,3532.75 4565.05,3532.75 4605.32,3532.75 4644.69,3532.75 4439.25,3571.03 4479.21,3571.03 4522.21,3571.03 4565.05,3571.03 4605.32,3571.03 4644.69,3571.03 4439.25,3610.39 4479.21,3610.39 4522.21,3610.39 4565.05,3610.39 4605.32,3610.39 4644.69,3610.39
NetC104_1: C104.1 R71.2 TP42.1 U2.29 | length 421.4
  Top Layer w10: TP42.1@3421,3190.52 3421,3130.92 3467.03,3084.89 3566.24,3084.89 3592.79,3111.43 C104.1@3592.79,3116.92 3596.91,3116.92 v1(3622.77,3091.06) 3638.87,3107.17 U2.29@3696.98,3107.17
  Bottom Layer w10: R71.2@3591.09,3092.65 R71.2@3592.55,3092.65 ; R71.2@3592.55,3085.81 3614.35,3085.81 v1@3621.19,3092.65
NetC107_1: C107.1 U2.28 | length 131.2
  Top Layer w10: C107.1@3585.72,3174.92 3633.79,3126.85 U2.28@3696.98,3126.85
NetC109_1: C109.1 R72.1 | length 41.9
  Top Layer w10: R72.1@3972.31,3112.76 C109.1@4014.23,3112.76
NetC109_2: C109.2 C110.1 L5.1 TP46.1 U2.8 U2.9 U2.10 U2.11 U2.12
NetC110_2: C110.2 R75.2 | length 87.3
  Top Layer w20: R75.2@3864.23,3508.46 3921.37,3508.46 C110.2@3942.67,3487.16
NetC131_1: C131.1 C142.1 J28.2 R76.1 R77.2 R78.1 U3.1 U3.18 U3.19 U3.20
NetC144_1: C144.1 U3.15 | length 61
  Top Layer w12: C144.1@819.96,1644.41 848.78,1644.41 857.42,1653.06 U3.15@877.43,1653.06
NetC145_1: C145.1 C147.1 J30.2 R81.1 R82.1 R83.2 U4.1 U4.18 U4.19 U4.20
NetC158_1: C158.1 U4.15 | length 61
  Top Layer w12: U4.15@3299.35,660.65 3299.35,640.65 3307.99,632 C158.1@3307.99,603.19
NetJ2_1: J2.1 R24.2 | length 126.4
  Top Layer w20: J2.1@4793.21,903.9 R24.2@4793.21,1030.27
NetJ5_1: J5.1 R33.2 | length 137.7
  Top Layer w20: R33.2@1080.63,2687.51 J5.1@1080.63,2825.22
NetJ9_1: J9.1 R37.2 | length 144.3
  Top Layer w20: J9.1@2467.12,3457.6 R37.2@2611.46,3457.6
NetJ11_1: J11.1 R38.2 | length 143
  Top Layer w20: J11.1@1925.57,691.33 R38.2@2068.6,691.33
NetJ13_1: J13.1 R45.2 | length 63.9
  Top Layer w20: J13.1@4555.25,1809.95 R45.2@4555.25,1873.82
NetJ26_1: J26.1 R74.2 | length 67.2
  Top Layer w20: R74.2@4976.13,4132.61 J26.1@4976.13,4199.81
NetJ27_1: J27.1 R78.2 | length 131.1
  Top Layer w20: J27.1@1120,1355.78 1124.91,1360.69 R78.2@1124.91,1484.82
NetJ29_1: J29.1 R82.2 | length 131.5
  Top Layer w20: R82.2@3476.12,911.87 3559.12,911.87 J29.1@3593.43,877.56
NetL1_1: L1.1 Q1.6 Q1.7 Q1.8 R25.2
NetL2_1: L2.1 Q2.6 Q2.7 Q2.8 R32.2
NetL4_1: L4.1 Q3.6 Q3.7 Q3.8 R46.2
NetQ1_3: Q1.3 R22.2 | length 196.4
  Top Layer w12: R22.2@2894.04,2044.59 2927.36,2044.59 2943.9,2061.13 2943.9,2095.29 2963.58,2114.97 3005.6,2114.97 3018.42,2102.15 Q1.3@3018.42,2084.59
NetQ1_5: Q1.5 R23.2 | length 113.5
  Top Layer w12: R23.2@2894.04,2003.59 2921.9,2003.59 2957.43,1968.06 Q1.5@2992.83,1968.06
NetQ2_3: Q2.3 R30.2 | length 207.5
  Top Layer w12: Q2.3@2072.59,2129.33 2072.59,2094.85 2086.35,2081.09 2109.4,2081.09 2122.42,2094.12 2122.42,2133.88 2156.13,2167.59 R30.2@2180.8,2167.59
NetQ2_5: Q2.5 R31.2 | length 96.8
  Top Layer w12: Q2.5@2098.18,2245.86 2136.18,2245.86 2170.45,2211.59 R31.2@2180.8,2211.59
NetQ3_3: Q3.3 R43.2 | length 155.1
  Top Layer w12: R43.2@2894.04,2167.59 2918.35,2167.59 2933.12,2182.37 2933.12,2247.73 2947.31,2261.92 Q3.3@2971.83,2261.92
NetQ3_5: Q3.5 R44.2 | length 274.5
  Top Layer w12: R44.2@2894.04,2126.59 2939.84,2126.59 2955.49,2142.24 3053.53,2142.24 3088.36,2177.07 Q3.5@3088.36,2236.33
NetR19_2: R19.2 S1.4 | length 91.9
  Top Layer w6: R19.2@565.93,3711.87 S1.4@565.93,3803.79
NetR60_2: R60.2 U2.36 | length 86.8
  Top Layer w10: U2.36@3781.63,3022.52 3781.63,2979.2 3792,2968.83 R60.2@3792,2940
NetR61_1: R61.1 TP39.1 U2.39 | length 364.4
  Top Layer w10: U2.39@3840.68,3022.52 3840.68,2982.42 3864.23,2958.88 3864.23,2845.2 3841.34,2822.31 R61.1@3841.34,2780 TP39.1@3944.03,2780
NetR62_1: R62.1 U2.37 | length 95.6
  Top Layer w10: U2.37@3801.31,3022.52 3801.31,2982.66 3833,2950.97 R62.1@3833,2940
NetR63_1: R63.1 R64.1 R66.2 TP40.1 | length 271.9
  Top Layer w10: TP40.1@3421,2866 R66.2@3580.23,2866 3582.04,2864.19 R63.1@3642.04,2864.19 R64.1@3642.04,2914.28
NetR64_2: R64.2 TP41.1 U2.33 | length 412.8
  Top Layer w10: TP41.1@3421,3029.52 3469.23,2981.29 3469.23,2958.66 3514.04,2913.85 3594.37,2913.85 R64.2@3642.04,2961.52 3670.25,2961.52 3722.57,3013.85 U2.33@3722.57,3022.52
NetR65_1: R65.1 U2.40 | length 86.5
  Top Layer w10: U2.40@3860.37,3022.52 3860.37,2989.42 3894.23,2955.56 R65.1@3894.23,2950
NetR67_1: R67.1 U2.2 | length 100.1
  Top Layer w10: U2.2@3885.96,3067.8 3896.1,3067.8 3957.52,3006.38 R67.1@3960.61,3006.38
NetR68_2: R68.2 U2.30 | length 120
  Top Layer w10: R68.2@3589.62,3056.92 3622.66,3056.92 3653.22,3087.48 U2.30@3696.98,3087.48
NetR69_1: R69.1 U2.3 | length 87.5
  Top Layer w10: U2.3@3885.96,3087.48 3920.04,3087.48 3951.15,3056.38 R69.1@3960.61,3056.38
NetR72_2: R72.2 U2.7 | length 88.9
  Top Layer w10: U2.7@3885.96,3166.22 3944.31,3166.22 3950.53,3160 R72.2@3972.31,3160
NetR76_2: R76.2 U3.9 | length 629.8
  Top Layer w10: v1(934.94,1826.86) 943.37,1818.43 U3.9@943.37,1795.77
  Top Layer w15: R76.2@1189.64,1627.17 v1(1232.68,1627.17)
  Bottom Layer w10: v1(934.94,1826.86) 921.89,1839.91 921.89,1881.24 944.54,1903.88 991.4,1903.88 1078.65,1816.64 1078.65,1718.3 1169.77,1627.17 v1(1232.68,1627.17)
NetR77_1: R77.1 R79.2 U3.16 | length 156.2
  Top Layer w12: U3.16@917.78,1612.7 917.78,1545.85 R79.2@915.26,1543.33 915.26,1535.34 R77.1@970.26,1480.34
NetR81_2: R81.2 U4.9 | length 643.7
  Top Layer w10: v1(3125.54,718.16) 3133.97,726.6 U4.9@3156.63,726.6
  Top Layer w15: R81.2@3317.12,969.92 v1(3317.12,1012.96)
  Bottom Layer w10: v1(3125.54,718.16) 3110.55,703.17 3069.62,703.17 3045.08,727.72 3045.08,762.5 3144.45,861.87 3266.12,861.87 3317.12,912.87 v1(3317.12,1012.96)
NetR83_1: R83.1 R84.2 U4.16 | length 156.2
  Top Layer w12: U4.16@3339.7,701.01 3406.55,701.01 3409.07,698.49 3417.06,698.49 R83.1@3472.06,753.49
SCL: J21.9 R56.2 U1.58 | length 2395.3
  Top Layer w6: R56.2@1051.26,3532.09 J21.9@1051.26,3776.19 ; v1(2370.8,2385.82) 2385.38,2371.24 2410.26,2371.24 2431.69,2349.81 2470.26,2349.81 2528.37,2291.7 U1.58@2528.37,2274.04
  Signal Layer 1 w6: J21.9@1051.26,3776.19 1051.26,3705.36 v1(2370.8,2385.82)
SDA: J21.10 R57.2 U1.59 | length 2371.2
  Top Layer w6: R57.2@1151.26,3532.09 J21.10@1151.26,3776.19 ; v1(2371.08,2355.94) 2409.59,2355.94 2426.71,2338.81 2464.61,2338.81 2512.62,2290.8 U1.59@2512.62,2274.04
  Signal Layer 1 w6: J21.10@1151.26,3776.19 1151.26,3635.05 2390.78,2395.53 2390.78,2375.64 v1(2371.08,2355.94)
SMBALERT: J22.8 TP43.1 U2.6 | length 2019.8
  Top Layer w10: U2.6@3885.96,3146.54 v1(3907.28,3146.54)
  Bottom Layer w6: v1(3907.28,3146.54) 3888.88,3146.54 3872.17,3129.82 3872.17,3100.69 3814.57,3043.09 3801.47,3043.09 3789.29,3030.91 3502.48,3030.91 3438.68,3094.71 3380.94,3094.71 3342.53,3133.12 3342.53,3255.77 TP43.1@3420,3333.24 3420,3393.75 3531.3,3505.05 3531.3,3607.25 4047.51,4123.46 J22.8@4047.51,4167.57
SW1: C18.1 Q1.4 U1.34 | length 476
  Top Layer w8: U1.34@2703.57,2020.11 v1(2732.85,2020.11)
  Top Layer w12: v1(2815.12,1920.59) C18.1@2846.42,1920.59 ; v1(2966.24,2084.59) Q1.4@2992.83,2084.59
  Signal Layer 1 w12: v1(2732.85,2020.11) 2732.85,2002.87 v1(2815.12,1920.59) 2848.99,1920.59 2892.14,1963.75 2892.14,2010.56 2941.49,2059.91 2941.49,2074.85 2951.23,2084.59 v1(2966.24,2084.59)
SW2: C31.1 Q2.4 U1.4 | length 529.9
  Top Layer w8: 2376.28,2193.33 U1.4@2400.42,2193.33
  Top Layer w10: 2345.14,2204.81 2356.62,2193.33 2376.28,2193.33
  Top Layer w12: v1(2098.18,2102.74) Q2.4@2098.18,2129.33 ; C31.1@2228.04,2294.59 v1(2255.36,2294.59) 2345.14,2204.81
  Signal Layer 1 w12: v1(2098.18,2102.74) 2101.04,2105.59 2155.63,2105.59 2199.18,2149.14 2199.18,2238.41 v1(2255.36,2294.59)
SW6: C71.1 Q3.4 U1.42 | length 452.6
  Top Layer w8: U1.42@2703.57,2146.09 2741.9,2146.09 2759.21,2163.4 v1(2780.69,2163.4)
  Top Layer w12: v1(2815.5,2253.59) C71.1@2846.8,2253.59 ; v1(2971.83,2209.74) Q3.4@2971.83,2236.33
  Signal Layer 1 w12: v1(2780.69,2163.4) 2758.59,2185.5 2758.59,2218.93 2793.25,2253.59 v1(2815.5,2253.59) 2905.66,2253.59 2949.51,2209.74 v1(2971.83,2209.74)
